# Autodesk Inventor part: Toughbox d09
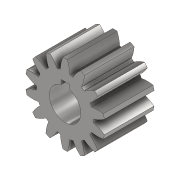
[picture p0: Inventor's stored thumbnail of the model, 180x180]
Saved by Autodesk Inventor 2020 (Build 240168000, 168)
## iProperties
Created: 2020-01
Part Number: Toughbox d09
Material: Steel, Alloy
Document SubType Name: Modeling
Designer: woodk
Density: 7.73 g/cm^3
Appearance: Semi-Polished
Vendor: KoP
Mass: 19.0841 g
Surface Area: 21.6285 cm^2
Volume: 2.46883 cm^3
Author: woodk
Revision Number: ANY
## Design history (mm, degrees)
feature "Imported1"
body "Solid1"
